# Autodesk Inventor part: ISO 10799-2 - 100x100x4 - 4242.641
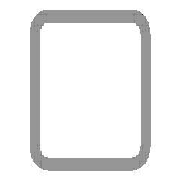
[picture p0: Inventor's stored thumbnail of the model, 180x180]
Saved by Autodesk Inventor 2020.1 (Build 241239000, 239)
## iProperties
Created: 2019-10
Part Number: ISO 10799-2 - 100x100x4 - 4242.641
Material: Stainless Steel
Description: Structural steels - Cold-formed, welded, structural hollow sections
Document SubType Name: Modeling
Standard: ISO
Designer: Synergysoft Dell02
Standard Revision: First edition 2011-09-15
Standards Organization: ISO
Language: en-US
Size Designation: 100x100x4
Categories: <MemberInstance><Categories><Category DisplayName="Structural Shapes" InternalName="089c4875-fa83-4c05-b084-43b9cc11f5ed" Mnemonic="GRDR"><CategoryParameter Dis
Stock Number: 100x100x4
Density: 8 g/cm^3
Appearance: Semi-Polished
_CCFamilyMember: 43
_CCFamilyDisplayName: ISO 10799-2 (Square) - Structural steels - Cold-formed, welded, structural hollow sections
_FrameMemberDoc: Frame Member File
_Version: 15.0.0
_GetPNFromCC: 1
G_L: 4242.641 mm
G_W: 100.000 mm
G_H: 100.000 mm
IsCustomPart: 1
Author: Synergysoft Dell02
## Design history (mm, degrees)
node "Start Plane"
node "End Plane"
sketch "Sketch"
  geometry: L1 (-50, -42)-(-50, 42); L2 (-42, 50)-(42, 50); L3 (50, 42)-(50, -42); L4 (42, -50)-(-42, -50); L5 (-42, 46)-(42, 46); L6 (46, 42)-(46, -42); L7 (42, -46)-(-42, -46); L8 (-46, -42)-(-46, 42); L9 (0, 72.32)-(0, -72.32) reference; L10 (-72.32, 0)-(72.32, 0) reference; A1 r 8 centre (-42, -42) between (-50, -42) and (-42, -50); A2 r 8 centre (42, 42) between (50, 42) and (42, 50); A3 r 8 centre (-42, 42) between (-42, 50) and (-50, 42); A4 r 8 centre (42, -42) between (42, -50) and (50, -42); A5 r 4 centre (-42, 42) between (-42, 46) and (-46, 42); A6 r 4 centre (42, 42) between (46, 42) and (42, 46); A7 r 4 centre (42, -42) between (42, -46) and (46, -42); A8 r 4 centre (-42, -42) between (-46, -42) and (-42, -46)
  constraints: 16 end point, 16 point on circle, 8 centre point, 8 tangent, 4 parallel, 3 equal radius, 2 perpendicular, 7 other
  dimensions: "d7" = 8 radius of A1 (= G_IR); "d9" = 100 distance between parallel lines of L1 L3 (= G_W); "d11" = 100 distance between parallel lines of L2 L4 (= G_H); "d12" = 4 distance between parallel lines of L3 L6 (= G_T); "d15" = 50 distance between parallel lines of L9 L3 (= 0.5 x d9); "d16" = 50 distance between parallel lines of L2 L10 (= 0.5 x d11)
extrude "Body" new body sketch "Sketch" stored distance "d3" = 4242.64069 (= G_L); taper "d4" = 0 deg
node "Driven Length"
  sketch "Sketch3"
    geometry: L1 (0, 0)-(10, 0) reference
    constraints: 2 end point, 1 horizontal
  workplane "Work Plane3"
  sketch "Sketch4"
    geometry: L1 (-2, 0)-(12, 0) reference; L2 (-2, 4242.641)-(12, 4242.641) reference
    dimensions: "d18" = 4242.64069 distance between parallel lines of L1 L2 (derived)
body "Solid1"
other parameters: "G_W" = 100 [user parameter; used in 1 equation term], "G_H" = 100 [user parameter; used in 1 equation term], "G_T" = 4 [user parameter; used in 1 equation term], "G_IR" = 8 [user parameter; used in 1 equation term], "G_L" = 4242.64069 (= d18) [user parameter; used in 1 equation term], "G_OFFSET_START" = 0 [user parameter; used in 1 equation term], "G_OFFSET_END" = 0 [user parameter; used in 1 equation term], "d13" = 0 (computed from G_OFFSET_START), "d14" = 4242.64069 (= G_OFFSET_END + B_L), "B_L" = 4242.64069 [user parameter; used in 1 equation term], "d17" = 90 deg, "MAS" = 1.17 [user parameter]
